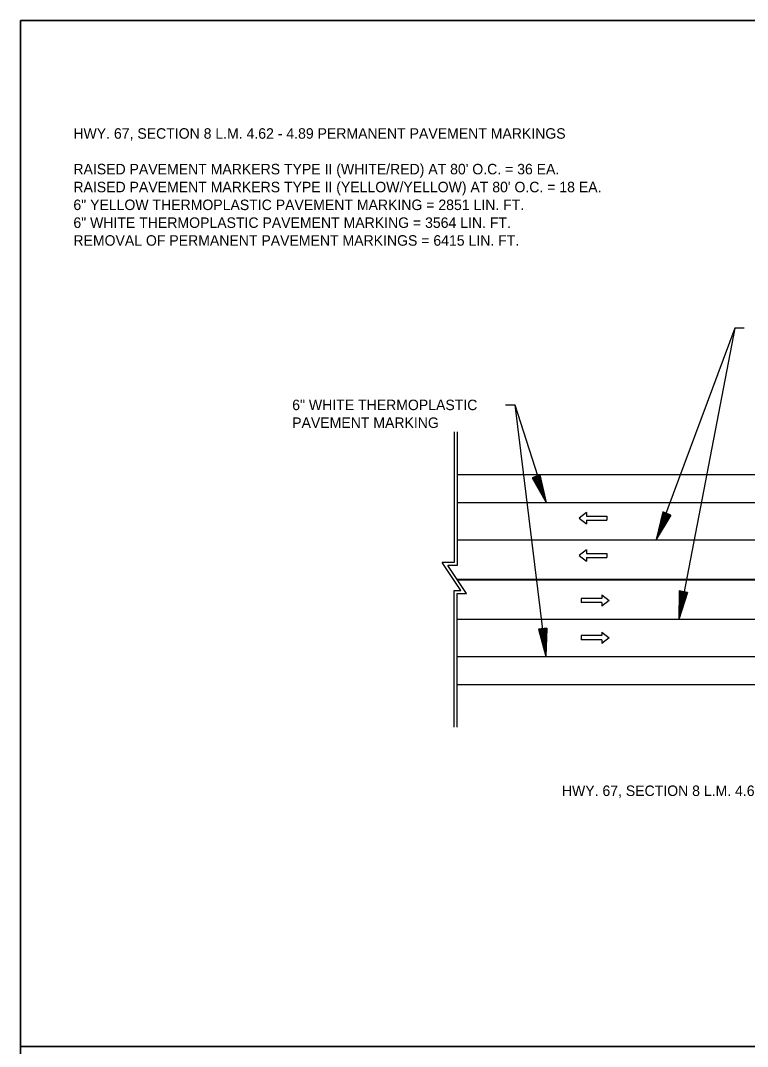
# Model space of a CAD drawing. Extents: x 1372926 to 1373096, y 381240 to 381790.
# Drawn here: x 1372926 to 1373003.9, y 381570.2 to 381680.2 of the extents above; entities that cross this region are included whole.
import ezdxf

# ---------------------------------------------------------------- set-up
doc = ezdxf.new("R2010")
doc.units = 0
for name, color, linetype in [('Default', 7, 'Continuous'), ('DSN_DRFT_Junk-No-Plot', 7, 'Continuous'), ('R_Draft', 7, 'Continuous')]:
    doc.layers.add(name, color=color, linetype=linetype)

msp = doc.modelspace()

# ---------------------------------------------------------------- linework, layer by layer
at = {"layer": 'Default'}
for p, q in [((1373002.53, 381647.2), (1372994.11, 381624.54)), ((1373002.53, 381647.2), (1372996.51, 381615.97)), ((1373003.53, 381647.2), (1373002.53, 381647.2)), ((1372977.95, 381638.96), (1372978.95, 381638.96)), ((1372978.95, 381638.96), (1372982.3, 381628.5)), ((1372978.95, 381638.96), (1372982.26, 381611.99)), ((1372972.44, 381636.08), (1372972.44, 381622.08)), ((1372972.78, 381636.08), (1372972.78, 381621.74)), ((1372981.64, 381631.46), (1372980.8, 381631.14)), ((1372980.8, 381631.14), (1372982.3, 381628.5)), ((1372980.87, 381631.16), (1372982.12, 381628.96)), ((1372980.95, 381631.19), (1372981.93, 381629.45)), ((1372981.02, 381631.22), (1372981.76, 381629.91)), ((1372981.09, 381631.24), (1372981.57, 381630.39)), ((1372981.16, 381631.27), (1372981.39, 381630.85)), ((1372981.29, 381631.32), (1372981.39, 381630.85)), ((1372981.36, 381631.35), (1372981.57, 381630.39)), ((1372981.43, 381631.38), (1372981.76, 381629.91)), ((1372981.5, 381631.4), (1372981.93, 381629.45)), ((1372981.57, 381631.43), (1372982.12, 381628.96)), ((1372981.64, 381631.46), (1372982.3, 381628.5)), ((1372986.61, 381627.41), (1372985.83, 381626.81)), ((1372986.61, 381627.41), (1372986.61, 381627.04)), ((1372994.81, 381627.49), (1372994.11, 381624.54)), ((1372994.88, 381627.46), (1372994.3, 381625)), ((1372994.96, 381627.43), (1372994.49, 381625.48)), ((1372995.02, 381627.4), (1372994.68, 381625.94)), ((1372995.65, 381627.15), (1372994.81, 381627.49)), ((1372985.83, 381626.81), (1372986.61, 381626.21)), ((1372986.61, 381627.04), (1372988.81, 381627.04)), ((1372986.61, 381626.59), (1372988.81, 381626.59)), ((1372986.61, 381626.59), (1372986.61, 381626.21)), ((1372988.81, 381627.04), (1372988.81, 381626.59)), ((1372995.65, 381627.15), (1372994.11, 381624.54)), ((1372995.58, 381627.18), (1372994.3, 381625)), ((1372995.51, 381627.21), (1372994.49, 381625.48)), ((1372995.44, 381627.24), (1372994.68, 381625.94)), ((1372995.1, 381627.37), (1372994.87, 381626.41)), ((1372995.37, 381627.27), (1372994.87, 381626.41)), ((1372995.17, 381627.35), (1372995.06, 381626.88)), ((1372995.3, 381627.29), (1372995.06, 381626.88)), ((1372986.61, 381623.41), (1372985.83, 381622.81)), ((1372986.61, 381623.41), (1372986.61, 381623.04)), ((1372986.61, 381623.04), (1372988.81, 381623.04)), ((1372988.81, 381623.04), (1372988.81, 381622.59)), ((1372973.16, 381619.08), (1372971.16, 381622.08)), ((1372972.44, 381622.08), (1372971.16, 381622.08)), ((1372985.83, 381622.81), (1372986.61, 381622.21)), ((1372986.61, 381622.59), (1372988.81, 381622.59)), ((1372986.61, 381622.59), (1372986.61, 381622.21)), ((1372972.78, 381621.74), (1372971.78, 381621.74)), ((1372973.78, 381618.74), (1372971.78, 381621.74)), ((1372972.44, 381619.08), (1372973.16, 381619.08)), ((1372972.44, 381604.41), (1372972.44, 381619.08)), ((1372972.78, 381604.41), (1372972.78, 381618.74)), ((1372972.78, 381618.74), (1372973.78, 381618.74)), ((1372996.56, 381619.01), (1372996.51, 381615.97)), ((1372997.45, 381618.86), (1372996.51, 381615.97)), ((1372997.45, 381618.86), (1372996.56, 381619.01)), ((1372996.64, 381618.99), (1372996.59, 381616.47)), ((1372997.38, 381618.87), (1372996.59, 381616.47)), ((1372996.71, 381618.98), (1372996.68, 381616.98)), ((1372997.3, 381618.88), (1372996.68, 381616.98)), ((1372996.79, 381618.97), (1372996.76, 381617.47)), ((1372997.23, 381618.9), (1372996.76, 381617.47)), ((1372996.86, 381618.96), (1372996.84, 381617.97)), ((1372997.15, 381618.91), (1372996.84, 381617.97)), ((1372996.94, 381618.94), (1372996.93, 381618.47)), ((1372997.08, 381618.92), (1372996.93, 381618.47)), ((1372988.26, 381618.22), (1372986.05, 381618.22)), ((1372986.05, 381618.22), (1372986.05, 381617.77)), ((1372988.26, 381617.77), (1372986.05, 381617.77)), ((1372988.26, 381618.59), (1372988.26, 381618.22)), ((1372988.26, 381618.59), (1372989.04, 381617.99)), ((1372989.04, 381617.99), (1372988.26, 381617.39)), ((1372988.26, 381617.77), (1372988.26, 381617.39)), ((1372982.39, 381615.02), (1372981.49, 381614.93)), ((1372981.49, 381614.93), (1372982.26, 381611.99)), ((1372981.57, 381614.93), (1372982.2, 381612.49)), ((1372981.64, 381614.94), (1372982.15, 381613)), ((1372981.72, 381614.95), (1372982.1, 381613.5)), ((1372981.79, 381614.96), (1372982.04, 381614)), ((1372981.87, 381614.97), (1372981.99, 381614.5)), ((1372982.01, 381614.98), (1372981.99, 381614.5)), ((1372982.09, 381614.99), (1372982.04, 381614)), ((1372982.16, 381615), (1372982.1, 381613.5)), ((1372982.24, 381615), (1372982.15, 381613)), ((1372982.31, 381615.01), (1372982.2, 381612.49)), ((1372982.39, 381615.02), (1372982.26, 381611.99)), ((1372988.26, 381614.22), (1372986.05, 381614.22)), ((1372986.05, 381614.22), (1372986.05, 381613.77)), ((1372988.26, 381614.59), (1372988.26, 381614.22)), ((1372988.26, 381614.59), (1372989.04, 381613.99)), ((1372988.26, 381613.77), (1372986.05, 381613.77)), ((1372989.04, 381613.99), (1372988.26, 381613.39)), ((1372988.26, 381613.77), (1372988.26, 381613.39))]:
    msp.add_line(p, q, dxfattribs=at)
for points in [[(1372925.97, 381680.17), (1372925.97, 381570.17), (1373095.97, 381570.17), (1373095.97, 381680.17)], [(1372925.97, 381570.17), (1372925.97, 381460.17), (1373095.97, 381460.17), (1373095.97, 381570.17)]]:
    msp.add_lwpolyline(points, close=True, dxfattribs=at)
at = {"layer": 'DSN_DRFT_Junk-No-Plot'}
for points in [[(1372925.97, 381680.17), (1373095.97, 381680.17), (1373095.97, 381570.17), (1372925.97, 381570.17)], [(1372925.97, 381680.17), (1372925.97, 381570.17), (1373095.97, 381570.17), (1373095.97, 381680.17)], [(1372925.97, 381570.17), (1373095.97, 381570.17), (1373095.97, 381460.17), (1372925.97, 381460.17)], [(1372925.97, 381570.17), (1372925.97, 381460.17), (1373095.97, 381460.17), (1373095.97, 381570.17)]]:
    msp.add_lwpolyline(points, close=True, dxfattribs=at)
at = {"layer": 'R_Draft'}
for p, q in [((1372972.78, 381631.49), (1373049.17, 381631.49)), ((1372972.78, 381628.49), (1373049.17, 381628.49)), ((1372972.78, 381624.49), (1373049.17, 381624.49)), ((1372972.74, 381620.29), (1373049.14, 381620.29)), ((1372972.81, 381620.19), (1373049.2, 381620.19)), ((1372972.78, 381615.99), (1373049.17, 381615.99)), ((1372972.78, 381611.99), (1373049.17, 381611.99)), ((1372972.78, 381608.99), (1373049.17, 381608.99))]:
    msp.add_line(p, q, dxfattribs=at)

# ---------------------------------------------------------------- texts
at = {"layer": 'Default'}
for s, p in [('HWY. 67, SECTION 8 L.M. 4.62 - 4.89 PERMANENT PAVEMENT MARKINGS', (1372931.64, 381667.5)), ("RAISED PAVEMENT MARKERS TYPE II (WHITE/RED) AT 80' O.C. = 36 EA.", (1372931.64, 381663.68)), ("RAISED PAVEMENT MARKERS TYPE II (YELLOW/YELLOW) AT 80' O.C. = 18 EA.", (1372931.64, 381661.76)), ('6" YELLOW THERMOPLASTIC PAVEMENT MARKING = 2851 LIN. FT.', (1372931.64, 381659.85)), ('6" WHITE THERMOPLASTIC PAVEMENT MARKING = 3564 LIN. FT.', (1372931.64, 381657.94)), ('REMOVAL OF PERMANENT PAVEMENT MARKINGS = 6415 LIN. FT.', (1372931.64, 381656.03)), ('6" WHITE THERMOPLASTIC', (1372955.09, 381638.4)), ('PAVEMENT MARKING', (1372955.09, 381636.49))]:
    msp.add_text(s, height=1.125, dxfattribs=at).set_placement(p)
at = {"layer": 'R_Draft'}
msp.add_text('HWY. 67, SECTION 8 L.M. 4.62 - 4.89 PERMANENT PAVEMENT MARKINGS', height=1.125, dxfattribs=at).set_placement((1372983.99, 381597.03))

doc.saveas('drawing.dxf')
